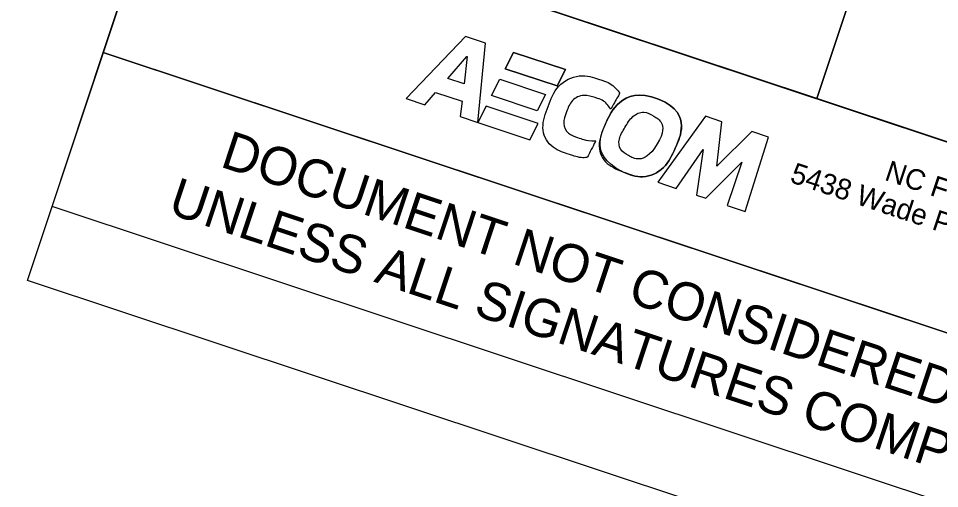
# Model space of a CAD drawing. Extents: x 2296288 to 2297455, y 600637 to 601606.
# Drawn here: x 2297286 to 2297365.9, y 601175.7 to 601216.5 of the extents above; entities that cross this region are included whole.
import ezdxf

# ---------------------------------------------------------------- set-up
doc = ezdxf.new("R2010")
doc.units = 0
for name, color, linetype in [('Default', 7, 'Continuous'), ('Exist DTM Drainline Cogo Comment', 7, 'Continuous'), ('Exist Property Iron Pin Cogo Number', 7, 'Continuous'), ('Exist Roads Curbs Cogo Comment', 7, 'Continuous'), ('Exist Roads Curbs Cogo Elevation', 7, 'Continuous'), ('Exist Roads EOP Cogo Comment', 7, 'Continuous'), ('Exist Roads EOP Other Cogo Point CELL', 7, 'Continuous')]:
    doc.layers.add(name, color=color, linetype=linetype)

# ---------------------------------------------------------------- blocks, each defined once
blk = doc.blocks.new('block 3')
at = {"layer": 'Default'}
blk.add_open_spline([(0.12275, 0.09393), (0.12554, 0.09373), (0.12726, 0.09146), (0.12695, 0.08843), (0.12663, 0.08531), (0.12411, 0.08298), (0.12127, 0.08318), (0.11848, 0.08338), (0.11676, 0.08565), (0.11707, 0.08868), (0.11739, 0.0918), (0.11991, 0.09413), (0.12275, 0.09393)], degree=3, dxfattribs=at)
blk = doc.blocks.new('block 2')
at = {"layer": 'Default'}
for p, q in [((0.10234, 0.09375), (0.10197, 0.09133)), ((0.10966, 0.09375), (0.10234, 0.09375)), ((0.10929, 0.09133), (0.10966, 0.09375)), ((0.10197, 0.09133), (0.10929, 0.09133)), ((0.10137, 0.08733), (0.10174, 0.08975)), ((0.10174, 0.08975), (0.10818, 0.08975)), ((0.10818, 0.08975), (0.10782, 0.08733)), ((0.10782, 0.08733), (0.10137, 0.08733)), ((0.10114, 0.08576), (0.10078, 0.08333)), ((0.10846, 0.08576), (0.10114, 0.08576)), ((0.1081, 0.08333), (0.10846, 0.08576)), ((0.10078, 0.08333), (0.1081, 0.08333))]:
    blk.add_line(p, q, dxfattribs=at)
for points in [[(0.10929, 0.09133), (0.10197, 0.09133), (0.10234, 0.09375), (0.10966, 0.09375), (0.10929, 0.09133)], [(0.10782, 0.08733), (0.10137, 0.08733), (0.10174, 0.08975), (0.10818, 0.08975), (0.10782, 0.08733)], [(0.10846, 0.08576), (0.10114, 0.08576), (0.10078, 0.08333), (0.1081, 0.08333), (0.10846, 0.08576)]]:
    blk.add_lwpolyline(points, dxfattribs=at)

msp = doc.modelspace()

# ---------------------------------------------------------------- linework, layer by layer
at = {"layer": 'Exist DTM Drainline Cogo Comment'}
for points in [[(2297319.596, 601292.554), (2297376.56, 601273.614), (2297355.263, 601209.561), (2297298.299, 601228.501)], [(2297376.56, 601273.614), (2297433.496, 601254.683), (2297412.199, 601190.63), (2297355.263, 601209.561)]]:
    msp.add_lwpolyline(points, close=True, dxfattribs=at)
at = {"layer": 'Exist Property Iron Pin Cogo Number'}
msp.add_lwpolyline([(2296425.754, 600981.215), (2297152.106, 600739.706), (2297168.672, 600769.147), (2297226.746, 600750.138), (2297369.397, 601166.292), (2297286.751, 601193.771), (2297317.24, 601285.466), (2296605.591, 601522.086)], close=True, dxfattribs=at)
at = {"layer": 'Exist Roads Curbs Cogo Comment'}
for p, q in [((2297288.881, 601200.177), (2297293.33, 601213.557)), ((2297293.33, 601213.557), (2297407.223, 601175.688)), ((2297402.774, 601162.308), (2297288.881, 601200.177))]:
    msp.add_line(p, q, dxfattribs=at)
at = {"layer": 'Exist Roads Curbs Cogo Elevation'}
msp.add_lwpolyline([(2296586.575, 601560.023), (2296387.821, 600962.212), (2297241.85, 600678.251), (2297402.771, 601162.301), (2297288.881, 601200.177), (2297326.705, 601313.933)], close=True, dxfattribs=at)
at = {"layer": 'Exist Roads EOP Cogo Comment'}
for p, q in [((2297324.754, 601214.956), (2297319.611, 601209.553)), ((2297326.49, 601214.379), (2297324.754, 601214.956)), ((2297325.839, 601207.482), (2297326.49, 601214.379)), ((2297323.22, 601211.307), (2297324.888, 601213.219)), ((2297324.903, 601213.214), (2297324.636, 601210.836)), ((2297324.888, 601213.219), (2297324.903, 601213.214)), ((2297324.636, 601210.836), (2297323.22, 601211.307)), ((2297321.222, 601209.017), (2297322.16, 601210.092)), ((2297322.16, 601210.092), (2297324.466, 601209.325)), ((2297319.611, 601209.553), (2297321.222, 601209.017)), ((2297324.466, 601209.325), (2297324.316, 601207.988)), ((2297324.316, 601207.988), (2297325.839, 601207.482)), ((2297345.58, 601208.032), (2297341.46, 601202.288)), ((2297347.022, 601207.552), (2297345.58, 601208.032)), ((2297346.567, 601203.691), (2297347.022, 601207.552)), ((2297349.618, 601206.69), (2297346.567, 601203.691)), ((2297349.049, 601199.765), (2297351.062, 601206.209)), ((2297351.062, 601206.209), (2297349.618, 601206.69)), ((2297343.052, 601201.759), (2297345.382, 601205.149)), ((2297345.382, 601205.149), (2297344.815, 601201.172)), ((2297345.627, 601200.903), (2297348.75, 601204.027)), ((2297348.75, 601204.027), (2297347.481, 601200.286)), ((2297341.46, 601202.288), (2297343.052, 601201.759)), ((2297344.815, 601201.172), (2297345.627, 601200.903)), ((2297347.481, 601200.286), (2297349.049, 601199.765))]:
    msp.add_line(p, q, dxfattribs=at)
for points in [[(2297324.316, 601207.988), (2297325.839, 601207.482), (2297326.49, 601214.379), (2297324.754, 601214.956), (2297319.611, 601209.553), (2297321.222, 601209.017), (2297322.16, 601210.092), (2297324.466, 601209.325), (2297324.316, 601207.988)], [(2297349.049, 601199.765), (2297351.062, 601206.209), (2297349.618, 601206.69), (2297346.567, 601203.691), (2297347.022, 601207.552), (2297345.58, 601208.032), (2297341.46, 601202.288), (2297343.052, 601201.759), (2297345.382, 601205.149), (2297344.815, 601201.172), (2297345.627, 601200.903), (2297348.75, 601204.027), (2297347.481, 601200.286), (2297349.049, 601199.765)]]:
    msp.add_lwpolyline(points, dxfattribs=at)
for points in [[(2297336.072, 601205.903), (2297335.577, 601205.848), (2297334.925, 601206.029), (2297334.61, 601206.133), (2297333.597, 601206.47), (2297333.156, 601207.385), (2297333.531, 601208.401), (2297333.928, 601209.474), (2297335.007, 601209.979), (2297336.121, 601209.609), (2297336.648, 601209.434), (2297337.054, 601209.106), (2297337.353, 601208.616), (2297337.353, 601208.616), (2297338.171, 601210.047), (2297338.171, 601210.047), (2297337.659, 601210.633), (2297337.177, 601210.964), (2297336.51, 601211.186), (2297334.665, 601211.799), (2297332.633, 601210.769), (2297331.927, 601208.86), (2297331.242, 601207.008), (2297332.021, 601205.287), (2297333.83, 601204.686), (2297334.144, 601204.582), (2297334.835, 601204.388), (2297335.33, 601204.444), (2297335.33, 601204.444), (2297336.072, 601205.903), (2297336.072, 601205.903)], [(2297336.072, 601205.903), (2297335.577, 601205.848), (2297334.925, 601206.029), (2297334.61, 601206.133), (2297333.597, 601206.47), (2297333.156, 601207.385), (2297333.531, 601208.401), (2297333.928, 601209.474), (2297335.007, 601209.979), (2297336.121, 601209.609), (2297336.648, 601209.434), (2297337.054, 601209.106), (2297337.353, 601208.616), (2297337.353, 601208.616), (2297338.171, 601210.047), (2297338.171, 601210.047), (2297337.659, 601210.633), (2297337.177, 601210.964), (2297336.51, 601211.186), (2297334.665, 601211.799), (2297332.633, 601210.769), (2297331.927, 601208.86), (2297331.242, 601207.008), (2297332.021, 601205.287), (2297333.83, 601204.686), (2297334.144, 601204.582), (2297334.835, 601204.388), (2297335.33, 601204.444), (2297335.33, 601204.444), (2297336.072, 601205.903), (2297336.072, 601205.903)], [(2297337.784, 601203.541), (2297336.6, 601204.371), (2297336.252, 601205.885), (2297336.952, 601207.439), (2297337.788, 601209.294), (2297339.814, 601210.209), (2297341.521, 601209.503)], [(2297341.521, 601209.503), (2297343.193, 601208.812), (2297343.789, 601207.065), (2297342.978, 601205.264), (2297342.142, 601203.409), (2297340.116, 601202.494), (2297338.409, 601203.2), (2297338.18, 601203.295), (2297337.971, 601203.409), (2297337.784, 601203.541)], [(2297341.403, 601205.615), (2297341.996, 601206.621), (2297341.873, 601207.598), (2297341.11, 601208.037), (2297340.272, 601208.521), (2297339.224, 601208.104), (2297338.597, 601207.042), (2297338.004, 601206.036), (2297338.127, 601205.059), (2297338.889, 601204.619), (2297339.729, 601204.136), (2297340.775, 601204.553), (2297341.403, 601205.615)], [(2297341.403, 601205.615), (2297341.996, 601206.621), (2297341.873, 601207.598), (2297341.11, 601208.037), (2297340.272, 601208.521), (2297339.224, 601208.104), (2297338.597, 601207.042), (2297338.004, 601206.036), (2297338.127, 601205.059), (2297338.889, 601204.619), (2297339.729, 601204.136), (2297340.775, 601204.553), (2297341.403, 601205.615)]]:
    msp.add_open_spline(points, degree=3, dxfattribs=at)
at = {"layer": 'Exist Roads EOP Other Cogo Point CELL'}
msp.add_lwpolyline([(2297298.299, 601228.501), (2297412.17, 601190.64), (2297407.201, 601175.695), (2297293.33, 601213.557)], close=True, dxfattribs=at)

# ---------------------------------------------------------------- block references
at = {"layer": 'Exist Roads EOP Cogo Comment', "xscale": 648.0018668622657, "yscale": 648.0018668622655, "rotation": -18.39175735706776}
for name in ['block 2', 'block 3']:
    msp.add_blockref(name, (2297246.835, 601176.844), dxfattribs=at)

# ---------------------------------------------------------------- texts
at = {"layer": 'Exist Roads Curbs Cogo Comment'}
for s, p in [('DOCUMENT NOT CONSIDERED FINAL', (2297303.368, 601203.678)), ('UNLESS ALL SIGNATURES COMPLETED', (2297298.815, 601199.627))]:
    msp.add_text(s, height=3.30002, rotation=341.60824, dxfattribs=at).set_placement(p)
at = {"layer": 'Exist Roads EOP Cogo Comment'}
for s, p in [('5438 Wade Park Boulevard, Suite 200', (2297352.835, 601202.328)), ('NC FIRM LICENSE No: F-0342', (2297361.046, 601202.514))]:
    msp.add_text(s, height=1.80001, rotation=341.60824, dxfattribs=at).set_placement(p)

doc.saveas('drawing.dxf')
